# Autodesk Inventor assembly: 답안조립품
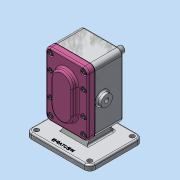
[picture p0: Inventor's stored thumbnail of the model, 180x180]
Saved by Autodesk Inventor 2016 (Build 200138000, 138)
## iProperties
Created: 2020-04
Part Number: 답안조립품
Material: 일반
Document SubType Name: Assembly
Designer: Administrator
Author: Administrator
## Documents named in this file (11)
- C:\Users\Administrator\Desktop\700407V1035\답안조립품.iam
- C:\Users\Administrator\Desktop\700407V1035\본체.ipt
- C:\Users\Administrator\Desktop\700407V1035\서브축.ipt
- C:\Users\Administrator\Desktop\700407V1035\키 6 x 6 x 18.ipt
- C:\Users\Administrator\Desktop\700407V1035\스퍼기어.ipt
- C:\Users\Administrator\Desktop\700407V1035\베어링부시.ipt
- C:\Users\Administrator\Desktop\700407V1035\메인축.ipt
- C:\Users\Administrator\Desktop\700407V1035\오일 실 16 28 7.ipt
- C:\Users\Administrator\Desktop\700407V1035\개스킷.ipt
- C:\Users\Administrator\Desktop\700407V1035\커버.ipt
- C:\Users\Administrator\Desktop\700407V1035\볼트 M5.ipt
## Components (1 placed, 1 different names)
1. 개스킷:1
